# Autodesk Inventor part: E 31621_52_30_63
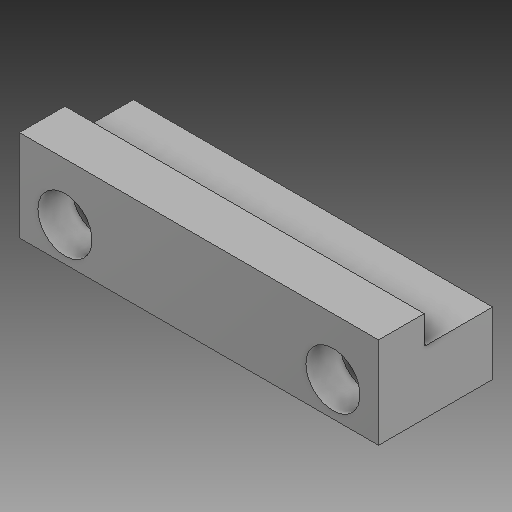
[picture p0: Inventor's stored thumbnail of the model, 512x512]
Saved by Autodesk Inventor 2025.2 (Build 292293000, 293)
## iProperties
Created: 2025-03
Part Number: E 31621_52_30_63
Material: Všeobecné
Document SubType Name: Modeling
Designer: Patrik
Density: 1 g/cm^3
Appearance: Výchozí
Mass: 14.8663 g
Surface Area: 57.9217 cm^2
Volume: 14.8663 cm^3
Author: Patrik
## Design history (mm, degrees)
feature "Base1"
node "Těleso1"
